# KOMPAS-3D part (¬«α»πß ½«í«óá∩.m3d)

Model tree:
1. Эскиз:1
2. Операция выдавливания:1
     Расстояние 1 = 2
3. Эскиз:3
4. Операция выдавливания:3
     Расстояние 1 = 2
5. Эскиз:4
6. Вырезать элемент выдавливания:1
     Расстояние 1 = 0.1
7. Фаска:3
     Угол = 78; Длина 1 = 1.8; Длина 2 = 8.46833
8. Эскиз:5
9. Операция выдавливания:4
     Расстояние 1 = 0.5
10. Эскиз:6
11. Вырезать элемент выдавливания:2
     Расстояние 1 = 0.5
12. Эскиз:7
13. Операция выдавливания:5
     Расстояние 1 = 0.5
14. Эскиз:8
15. Вырезать элемент выдавливания:3
     Расстояние 1 = 0.4
16. Эскиз:9
17. Вырезать элемент выдавливания:4
     Расстояние 1 = 0.5
18. Эскиз:10
19. Операция выдавливания:6
     Расстояние 1 = 0.5
20. Эскиз:11
21. Операция выдавливания:7
     Расстояние 1 = 0.5
22. Эскиз:12
23. Операция выдавливания:8
     Расстояние 1 = 0.2
24. Эскиз:13
25. Вырезать элемент выдавливания:5
     Расстояние 1 = 0.2
26. Эскиз:14
27. Операция выдавливания:9
     Расстояние 1 = 2
28. Эскиз:15
29. Операция выдавливания:10
     Расстояние 1 = 0.5
30. Эскиз:16
31. Вырезать элемент выдавливания:6
     Расстояние 1 = 2
32. Эскиз:17
33. Операция выдавливания:11
     Расстояние 1 = 2
34. Эскиз:18
35. Операция выдавливания:12
     Расстояние 1 = 0.5
36. Эскиз:19
37. Вырезать элемент выдавливания:7
     Расстояние 1 = 0.5
38. Эскиз:20
39. Операция выдавливания:13
     Расстояние 1 = 0.5
40. Эскиз:21
41. Вырезать элемент выдавливания:8
     Расстояние 1 = 0.4
42. Эскиз:22
43. Вырезать элемент выдавливания:9
     Расстояние 1 = 0.5
44. Эскиз:23
45. Операция выдавливания:14
     Расстояние 1 = 0.5
46. Эскиз:24
47. Операция выдавливания:15
     Расстояние 1 = 0.5
48. Эскиз:25
49. Вырезать элемент выдавливания:10
     Расстояние 1 = 0.2
50. Эскиз:26
51. Операция выдавливания:16
     Расстояние 1 = 7; Расстояние 2 = 8.2
52. Эскиз:27
53. Вырезать элемент выдавливания:11
     Расстояние 1 = 10
54. Эскиз:28
55. Операция выдавливания:17
     Расстояние 1 = 0.5
56. Эскиз:29
57. Вырезать элемент выдавливания:12
     Расстояние 1 = 0.3
58. Скругление:2
     Радиус = 0.3
59. Скругление:3
     Радиус = 0.3
60. Скругление:4
     Радиус = 0.3
61. Скругление:5
     Радиус = 0.3
62. Скругление:6
     Радиус = 1
63. Скругление:7
     Радиус = 0.2
64. Эскиз:30
65. Операция выдавливания:18
     Расстояние 1 = 2
66. Эскиз:31
67. Вырезать элемент выдавливания:13
     Расстояние 1 = 128
68. Эскиз:32
69. Операция выдавливания:19
     Расстояние 1 = 2.2
70. Эскиз:33
71. Операция выдавливания:20
     Расстояние 1 = 2
72. Эскиз:34
73. Вырезать элемент выдавливания:14
     Расстояние 1 = 2
74. Эскиз:35
75. Вырезать элемент выдавливания:15
     Расстояние 1 = 0.5
76. Эскиз:36
77. Вырезать элемент выдавливания:16
     Расстояние 1 = 0.5
78. Эскиз:37
79. Операция выдавливания:21
     Расстояние 1 = 0.2
80. Эскиз:38
81. Операция выдавливания:22
     Расстояние 1 = 0.1
82. Эскиз:39
83. Вырезать элемент выдавливания:17
     Расстояние 1 = 0.2
84. Эскиз:40
85. Вырезать элемент выдавливания:18
     Расстояние 1 = 0.5
86. Эскиз:41
87. Операция выдавливания:23
     Расстояние 1 = 0.1
88. Эскиз:42
89. Вырезать элемент выдавливания:19
     Расстояние 1 = 0.2
90. Эскиз:43
91. Операция выдавливания:24
     Расстояние 1 = 2.5
92. Эскиз:44
93. Вырезать элемент выдавливания:20
     Расстояние 1 = 20
94. Эскиз:45
95. Вырезать элемент выдавливания:21
     Расстояние 1 = 20
96. Скругление:10
     Радиус = 0.1
97. Фаска:4
     Угол = 63.4349; Длина 1 = 1; Длина 2 = 2
98. Эскиз:46
99. Вырезать элемент выдавливания:22
     Расстояние 1 = 115.991
100. Эскиз:47
101. Операция выдавливания:25
     Расстояние 1 = 0.3
102. Скругление:11
     Радиус = 0.3
103. Эскиз:48
104. Вырезать элемент выдавливания:23
     Расстояние 1 = 0.3

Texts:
  корпус лобовая  низ
  Сплав АЛ8  ГОСТ 1583-93
  stalker61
